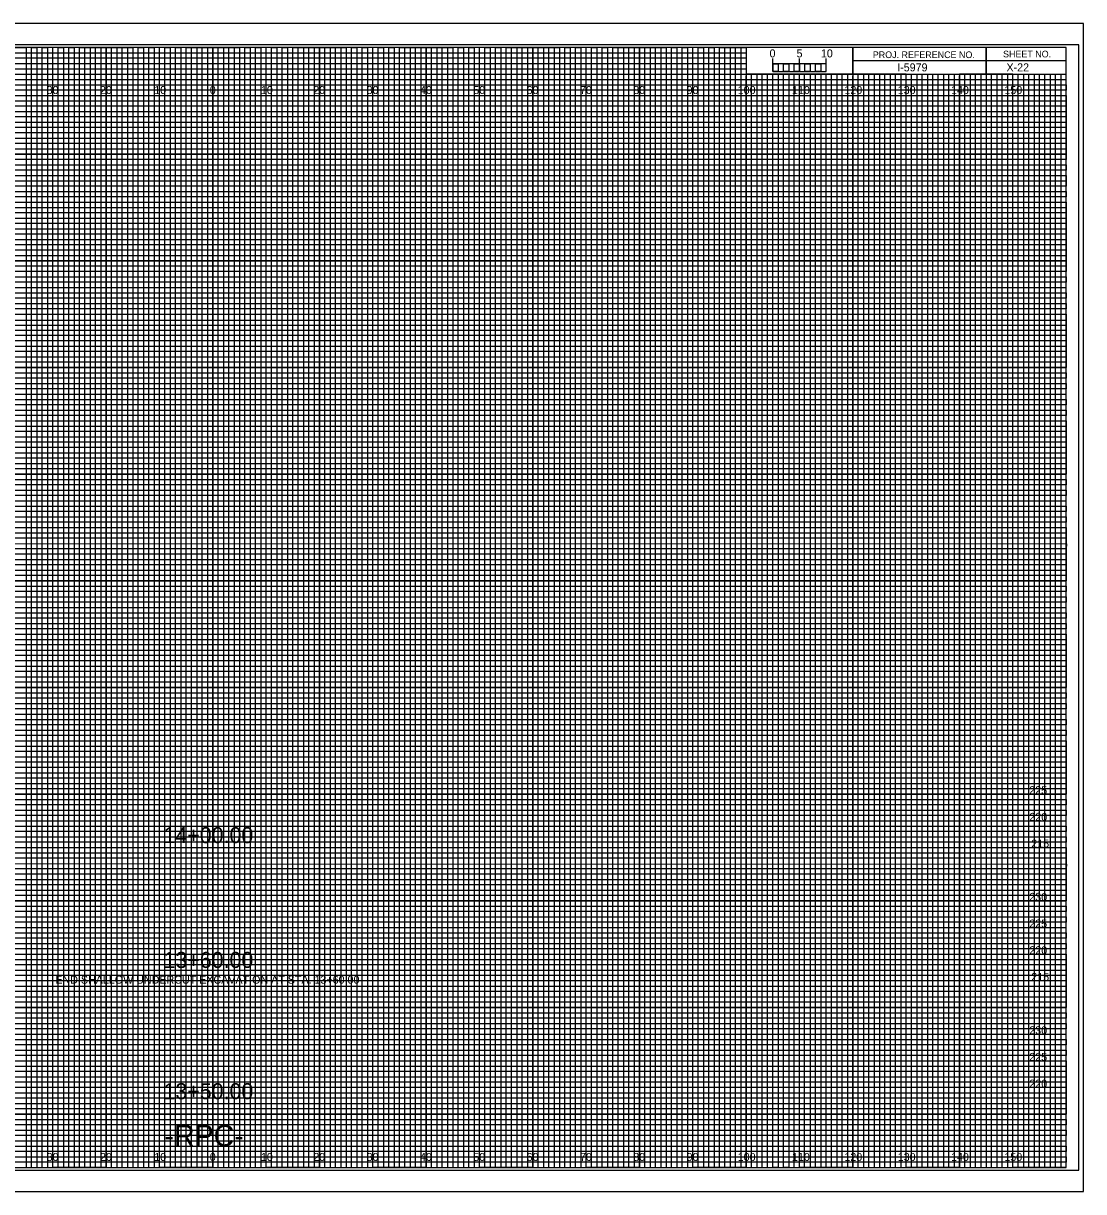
# Model space of a CAD drawing. Extents: x -13 to 323, y -5 to 434.
# Drawn here: x 124.5 to 323.3, y 215.5 to 434.5 of the extents above; entities that cross this region are included whole.
import ezdxf

# ---------------------------------------------------------------- set-up
doc = ezdxf.new("R2010")
doc.units = 0
for name, color, linetype in [('Prop XS Alignment Label', 7, 'Continuous'), ('Prop XS Bar Scale Labels', 7, 'Continuous'), ('Prop XS Elevation Labels', 7, 'Continuous'), ('Prop XS Hydro Elevations', 7, 'Continuous'), ('Prop XS Offset Labels', 7, 'Continuous'), ('Prop XS Project Number', 7, 'Continuous'), ('Prop XS Sheet Number', 7, 'Continuous'), ('Prop XS Station Labels', 7, 'Continuous'), ('Sheet Cross Section CELL', 7, 'Continuous'), ('Sheet Cross Section Grid Major CELL', 7, 'Continuous'), ('Sheet Cross Section Grid Middle CELL', 7, 'Continuous'), ('Sheet Cross Section Grid Minor 1 CELL', 7, 'Continuous'), ('Sheet Cross Section Grid Minor 2 CELL', 7, 'Continuous'), ('Sheet Cross Section Scale CELL', 7, 'Continuous'), ('Sheet Cutting Line CELL', 7, 'Continuous'), ('Sheet DOT Grid CELL', 7, 'Continuous'), ('Sheet Plot Border Inside CELL', 7, 'Continuous'), ('Sheet Plot Border Outside CELL', 7, 'Continuous')]:
    doc.layers.add(name, color=color, linetype=linetype)

msp = doc.modelspace()

# ---------------------------------------------------------------- linework, layer by layer
at = {"layer": 'Sheet Cross Section CELL'}
for p, q in [((305, 430), (305, 425)), ((305, 425), (305, 430)), ((280, 427.5), (280, 425)), ((320, 427.49), (280, 427.49)), ((280, 425), (320, 425))]:
    msp.add_line(p, q, dxfattribs=at)
for points in [[(320, 430), (0, 430), (0, 220), (320, 220)], [(280, 430), (260, 430), (260, 425.03), (280, 425.03)], [(320, 430), (280, 430), (280, 425), (320, 425)]]:
    msp.add_lwpolyline(points, close=True, dxfattribs=at)
at = {"layer": 'Sheet Cross Section Grid Major CELL'}
for p, q in [((130, 430), (120, 430)), ((130, 220), (130, 430)), ((150, 430), (140, 430)), ((140, 430), (140, 220)), ((150, 220), (150, 430)), ((170, 430), (160, 430)), ((160, 430), (160, 220)), ((170, 220), (170, 430)), ((190, 430), (180, 430)), ((180, 430), (180, 220)), ((190, 220), (190, 430)), ((210, 430), (200, 430)), ((200, 430), (200, 220)), ((210, 220), (210, 430)), ((230, 430), (220, 430)), ((220, 430), (220, 220)), ((230, 220), (230, 430)), ((250, 430), (240, 430)), ((240, 430), (240, 220)), ((250, 220), (250, 430)), ((260, 430), (260, 220)), ((270, 220), (270, 425)), ((290, 425), (280, 425)), ((280, 425), (280, 220)), ((290, 220), (290, 425)), ((310, 425), (300, 425)), ((300, 425), (300, 220)), ((310, 220), (310, 425)), ((140, 220), (130, 220)), ((160, 220), (150, 220)), ((180, 220), (170, 220)), ((200, 220), (190, 220)), ((220, 220), (210, 220)), ((240, 220), (230, 220)), ((260, 220), (250, 220)), ((280, 220), (270, 220)), ((300, 220), (290, 220)), ((320, 220), (310, 220)), ((320, 220), (320, 220))]:
    msp.add_line(p, q, dxfattribs=at)
for points in [[(0, 420), (320, 420), (320, 410), (0, 410)], [(0, 400), (320, 400), (320, 390), (0, 390)], [(0, 380), (320, 380), (320, 370), (0, 370)], [(0, 360), (320, 360), (320, 350), (0, 350)], [(0, 340), (320, 340), (320, 330), (0, 330)], [(0, 320), (320, 320), (320, 310), (0, 310)], [(0, 300), (320, 300), (320, 290), (0, 290)], [(0, 280), (320, 280), (320, 270), (0, 270)], [(0, 260), (320, 260), (320, 250), (0, 250)], [(0, 240), (320, 240), (320, 230), (0, 230)]]:
    msp.add_lwpolyline(points, dxfattribs=at)
at = {"layer": 'Sheet Cross Section Grid Middle CELL'}
for points in [[(115, 430), (125, 430), (125, 220), (135, 220), (135, 430), (145, 430), (145, 220), (155, 220), (155, 430), (165, 430), (165, 220), (175, 220), (175, 430), (185, 430), (185, 220), (195, 220), (195, 430), (205, 430), (205, 220), (215, 220), (215, 430), (225, 430), (225, 220), (235, 220), (235, 430), (245, 430), (245, 220), (255, 220), (255, 430), (259.93, 430), (260, 430), (260, 425), (264.99, 425), (264.99, 220), (275, 220), (275, 425), (285, 425), (285, 220), (295, 220), (295, 425), (305, 425), (305, 220), (315, 220), (315, 425)], [(0, 425), (275, 425)], [(0, 405), (320, 405), (320, 415), (0, 415)], [(0, 385), (320, 385), (320, 395), (0, 395)], [(0, 365), (320, 365), (320, 375), (0, 375)], [(0, 345), (320, 345), (320, 355), (0, 355)], [(0, 325), (320, 325), (320, 335), (0, 335)], [(0, 305), (320, 305), (320, 315), (0, 315)], [(0, 285), (320, 285), (320, 295), (0, 295)], [(0, 265), (320, 265), (320, 275), (0, 275)], [(0, 245), (320, 245), (320, 255), (0, 255)], [(0, 225), (320, 225), (320, 235), (0, 235)]]:
    msp.add_lwpolyline(points, dxfattribs=at)
at = {"layer": 'Sheet Cross Section Grid Minor 1 CELL'}
for p, q in [((0, 429), (260, 429)), ((260, 427.98), (0, 427.98)), ((260, 429), (260, 427.98)), ((0, 427), (260, 427)), ((260, 425.89), (0, 425.89)), ((260, 427), (260, 425.89)), ((0, 424), (320, 424))]:
    msp.add_line(p, q, dxfattribs=at)
for points in [[(0, 423), (270, 423), (320, 423), (320, 422), (0, 422)], [(0, 421), (320, 421), (320, 419), (0, 419)], [(0, 418), (320, 418), (320, 417), (0, 416.98)], [(0, 416), (320, 416), (320, 414), (0, 414)], [(0, 413), (320, 413), (320, 412), (0, 412)], [(0, 411), (320, 411), (320, 409), (0, 409)], [(0, 408), (320, 408), (320, 407), (0, 407)], [(0, 406), (320, 406), (320, 404), (0, 404)], [(0, 403), (320, 403), (320, 402), (0, 402)], [(0, 401), (320, 401), (320, 399), (0, 399)], [(0, 398), (320, 398), (320, 397), (0, 397)], [(0, 396), (320, 396), (320, 393.95), (320, 393), (320, 392), (0, 392)], [(0, 394), (320, 394), (320, 393), (0, 393)], [(0, 391), (320, 391), (320, 389), (0, 389.03)], [(0, 389.03), (320, 389), (320, 388), (0, 388)], [(0, 387), (320, 387), (320, 386), (0, 386)], [(0, 384), (320, 384), (320, 383), (0, 383)], [(0, 382), (320, 382), (320, 381), (0, 381)], [(-0.07, 378.89), (320, 378.89), (320, 377.88), (-0.07, 377.88)], [(0, 377), (320, 377), (320, 376), (0, 376)], [(0, 374), (320, 374), (320, 373), (0, 373)], [(0, 372), (320, 372), (320, 371), (0, 371)], [(0, 369), (320, 369), (320, 368), (0, 368)], [(0, 367), (320, 367), (320, 366), (0, 366)], [(0, 364), (320, 364), (320, 363), (0, 363)], [(0, 362), (320, 362), (320, 361), (0, 361)], [(0, 359), (320, 359), (319.99, 357.98), (0, 358)], [(0, 357), (320, 357), (320, 356), (0, 356)], [(0, 354), (320, 354), (320, 353), (0, 353)], [(0, 352), (320, 352), (320, 351), (0, 351)], [(0, 349), (320, 349), (320, 348), (0, 348)], [(0, 347), (320, 347), (320, 346), (0, 346)], [(0, 344), (320, 344), (320, 343), (0, 343)], [(0, 342), (320, 342), (320, 341), (0, 341)], [(0, 339), (320, 339), (320, 338), (0, 338)], [(0, 336.99), (320.07, 336.91), (320, 336), (0, 336)], [(0, 334), (320, 334), (320, 333), (0, 333)], [(0, 332), (320, 332), (320, 331), (0, 331)], [(0, 329), (320, 329), (320, 328), (0, 328)], [(0, 327), (320, 327), (320, 326), (0, 326)], [(0, 324), (320, 324), (320, 323), (0, 323)], [(0, 322), (320, 322), (320, 321), (0, 321)], [(0, 319), (320, 319), (320, 318), (0, 318)], [(0, 317), (320, 317), (320, 316), (0, 316)], [(0, 314), (320, 314), (320, 313), (0, 313)], [(0, 312), (320, 312), (320, 311), (0, 311)], [(0, 309), (320, 309), (320, 308), (0, 308)], [(0, 307), (320, 307), (320, 306), (0, 306)], [(0, 304), (320, 304), (320, 303), (0, 303)], [(0, 302), (320, 302), (320, 301), (0, 301)], [(0, 299), (320, 299), (319.99, 297.98), (0, 298)], [(0, 297), (320, 297), (320, 296), (0, 296)], [(0, 294), (320, 294), (320, 293), (0, 293)], [(0, 292), (320, 292), (320, 291), (0, 291)], [(0, 289), (320, 289), (320, 288), (0, 288)], [(0, 287), (320, 287), (320, 286), (0, 286)], [(0, 284), (320, 284), (320, 283), (0, 283)], [(0, 282), (320, 282), (320, 281), (0, 281)], [(0, 279), (320, 279), (320, 278), (0, 278)], [(0, 276.99), (320.07, 276.91), (320, 276), (0, 276)], [(0, 274), (320, 274), (320, 273), (0, 273)], [(0, 272), (320, 272), (320, 271), (0, 271)], [(0, 269), (320, 269), (320, 268), (0, 268)], [(0, 267), (320, 267), (320, 266), (0, 266)], [(0, 264), (320, 264), (320, 263), (0, 263)], [(0, 262), (320, 262), (320, 261), (0, 261)], [(0, 259), (320, 259), (320, 258), (0, 258)], [(0, 257), (320, 257), (320, 256), (0, 256)], [(0, 254), (320, 254), (320, 253), (0, 253)], [(0, 252), (320, 252), (320, 251), (0, 251)], [(0, 249), (320, 249), (320, 248), (0, 248)], [(0, 247), (320, 247), (320, 246), (0, 246)], [(0, 244), (320, 244), (320, 243), (0, 243)], [(0, 242), (320, 242), (320, 241), (0, 241)], [(0, 239), (320, 239), (320, 238), (0, 238)], [(0, 237), (320, 237), (320, 236), (0, 236)], [(0, 234), (320, 234), (320, 233), (0, 233)], [(0, 232), (320, 232), (320, 231), (0, 231)], [(0, 229), (320, 229), (320, 228), (0, 228)], [(0, 227), (320, 227), (320, 226), (0, 226)], [(0, 224), (320, 224), (320, 223), (0, 223)], [(0, 222), (320, 222), (320, 221), (0, 221)]]:
    msp.add_lwpolyline(points, dxfattribs=at)
at = {"layer": 'Sheet Cross Section Grid Minor 2 CELL'}
for p, q in [((267, 425), (266.01, 425)), ((266.01, 425), (266.01, 220)), ((267, 220), (267, 425)), ((269, 425), (268, 425)), ((268, 425), (268, 220)), ((269, 220), (269, 425)), ((266.01, 220), (265, 220)), ((268, 220), (267, 220))]:
    msp.add_line(p, q, dxfattribs=at)
for points in [[(125, 220), (126, 220), (126, 430), (127, 430), (127, 220)], [(127, 220), (128, 220), (128, 430), (129, 430), (129, 220)], [(130, 220), (131, 220), (131, 430), (132, 430), (132, 220)], [(132, 220), (133, 220), (133, 430), (134, 430), (134, 220)], [(135, 220), (136, 220), (136, 430), (137, 430), (137, 220)], [(137, 220), (138, 220), (138, 430), (139, 430), (139, 220)], [(140, 220), (141, 220), (141, 430), (142, 430), (142, 220)], [(142, 220), (143, 220), (143, 430), (144, 430), (144, 220)], [(145, 220), (146, 220), (146, 430), (147, 430), (147, 220)], [(147, 220), (148, 220), (148, 430), (149, 430), (149, 220)], [(150, 220), (151, 220), (151, 430), (152, 430), (152, 220)], [(152, 220), (153, 220), (153, 430), (154, 430), (154, 220)], [(155, 220), (156, 220), (156, 430), (157, 430), (157, 220)], [(157, 220), (158, 220), (158, 430), (159, 430), (159, 220)], [(160, 220), (161, 220), (161, 430), (162, 430), (162, 220)], [(162, 220), (163, 220), (163, 430), (164, 430), (164, 220)], [(165, 220), (166, 220), (166, 430), (167, 430), (167, 220)], [(167, 220), (168, 220), (168, 430), (169, 430), (169, 220)], [(170, 220), (171, 220), (171, 430), (172, 430), (172, 220)], [(172, 220), (173, 220), (173, 430), (174, 430), (174, 220)], [(175, 220), (176, 220), (176, 430), (177, 430), (177, 220)], [(177, 220), (178, 220), (178, 430), (179, 430), (179, 220)], [(180, 220), (181, 220), (181, 430), (182, 430), (182, 220)], [(182, 220), (183, 220), (183, 430), (184, 430), (184, 220)], [(185, 220), (186, 220), (186, 430), (187, 430), (187, 220)], [(187, 220), (188, 220), (188, 430), (189, 430), (189, 220)], [(190, 220), (191, 220), (191, 430), (192, 430), (192, 220)], [(192, 220), (193, 220), (193, 430), (194, 430), (194, 220)], [(195, 220), (196, 220), (196, 430), (197, 430), (197, 220)], [(197, 220), (198, 220), (198, 430), (199, 430), (199, 220)], [(200, 220), (201, 220), (201, 430), (202, 430), (202, 220)], [(202, 220), (203, 220), (203, 430), (204, 430), (204, 220)], [(205, 220), (206, 220), (206, 430), (207, 430), (207, 220)], [(207, 220), (208, 220), (208, 430), (209, 430), (209, 220)], [(210, 220), (211, 220), (211, 430), (212, 430), (212, 220)], [(212, 220), (213, 220), (213, 430), (214, 430), (214, 220)], [(215, 220), (216, 220), (216, 430), (217, 430), (217, 220)], [(217, 220), (218, 220), (218, 430), (219, 430), (219, 220)], [(220, 220), (221, 220), (221, 430), (222, 430), (222, 220)], [(222, 220), (223, 220), (223, 430), (224, 430), (224, 220)], [(225, 220), (226, 220), (226, 430), (227, 430), (227, 220)], [(227, 220), (228, 220), (228, 430), (229, 430), (229, 220)], [(230, 220), (231, 220), (231, 430), (232, 430), (232, 220)], [(232, 220), (233, 220), (233, 430), (234, 430), (234, 220)], [(235, 220), (236, 220), (236, 430), (237, 430), (237, 220)], [(237, 220), (238, 220), (238, 430), (239, 430), (239, 220)], [(240, 220), (241, 220), (241, 430), (242, 430), (242, 220)], [(242, 220), (243, 220), (243, 430), (244, 430), (244, 220)], [(245, 220), (246, 220), (246, 430), (247, 430), (247, 220)], [(247, 220), (248, 220), (248, 430), (249, 430), (249, 220)], [(250, 220), (251, 220), (251, 430), (252, 430), (252, 220)], [(252, 220), (253, 220), (253, 430), (254, 430), (254, 220)], [(255, 220), (256, 220), (256, 430), (257, 430), (257, 220)], [(257, 220), (258, 220), (258, 430), (259, 430), (259, 220)], [(260, 220), (261, 220), (261, 425), (262.02, 425), (262.02, 220)], [(262, 220), (263, 220), (263, 425), (263.99, 425), (263.99, 220)], [(270, 220), (270.98, 220), (270.98, 425), (272, 425), (272, 220)], [(272, 220), (273, 220), (273, 425), (274.05, 425), (274.05, 220)], [(275, 220), (276, 220), (276, 425), (277, 425), (277, 220)], [(277, 220), (278, 220), (278, 425), (279, 425), (279, 220)], [(280, 220), (281, 220), (281, 425), (282, 425), (282, 220)], [(282, 220), (283, 220), (283, 425), (284, 425), (284, 220)], [(285, 220), (286, 220), (286, 425), (287, 425), (287, 220)], [(287, 220), (288, 220), (288, 425), (289, 425), (289, 220)], [(290, 220), (291, 220), (291, 425), (292, 425), (292, 220)], [(292, 220), (293, 220), (293, 425), (294, 425), (294, 220)], [(295, 220), (296, 220), (296, 425), (297, 425), (297, 220)], [(297, 220), (298, 220), (298, 425), (299, 425), (299, 220)], [(300, 220), (301, 220), (301, 425), (302, 425), (302, 220)], [(302, 220), (303, 220), (303, 425), (304, 425), (304, 220)], [(305, 220), (306, 220), (306, 425), (307, 425), (307, 220)], [(307, 220), (308, 220), (308, 425), (309, 425), (309, 220)], [(310, 220), (311, 220), (311, 425), (312, 425), (312, 220)], [(312, 220), (313, 220), (313, 425), (314, 425), (314, 220)], [(315, 220), (316, 220), (316, 425), (317, 425), (317, 220)], [(317, 220), (318, 220), (318, 425), (319, 425), (319, 220)]]:
    msp.add_lwpolyline(points, dxfattribs=at)
at = {"layer": 'Sheet Cross Section Scale CELL'}
for p, q in [((265, 425.49), (265, 427.9)), ((265, 426.9), (265, 427.9)), ((270, 425.49), (270, 427.9)), ((275, 425.49), (275, 427.9)), ((275, 426.9), (275, 427.9))]:
    msp.add_line(p, q, dxfattribs=at)
for points in [[(275, 426.9), (265, 426.9), (265, 425.49), (275, 425.49)], [(265, 426.9), (266, 426.9), (266, 425.49), (265, 425.49)], [(267, 426.9), (268, 426.9), (268, 425.49), (267, 425.49)], [(269, 426.9), (270, 426.9), (270, 425.49), (269, 425.49)], [(271, 426.9), (272, 426.9), (272, 425.49), (271, 425.49)], [(273, 426.9), (274, 426.9), (274, 425.49), (273, 425.49)]]:
    msp.add_lwpolyline(points, close=True, dxfattribs=at)
at = {"layer": 'Sheet Cutting Line CELL'}
for p, q in [((323.3, 434.5), (-13.4, 434.5)), ((-13.4, 215.5), (323.3, 215.5))]:
    msp.add_line(p, q, dxfattribs=at)
at = {"layer": 'Sheet DOT Grid CELL'}
for p, q in [((130, 220), (130, 430)), ((140, 220), (140, 430)), ((150, 220), (150, 430)), ((160, 220), (160, 430)), ((170, 220), (170, 430)), ((180, 220), (180, 430)), ((190, 220), (190, 430)), ((200, 220), (200, 430)), ((210, 220), (210, 430)), ((220, 220), (220, 430)), ((230, 220), (230, 430)), ((240, 220), (240, 430)), ((250, 220), (250, 430)), ((260, 220), (260, 424.69)), ((270, 220), (270, 424.69)), ((280, 220), (280, 424.69)), ((290, 220), (290, 424.69)), ((300, 220), (300, 424.69)), ((310, 220), (310, 424.69)), ((0, 420), (320, 420)), ((0, 410), (320, 410)), ((0, 400), (320, 400)), ((0, 390), (320, 390)), ((0, 380), (320, 380)), ((0, 370), (320, 370)), ((0, 360), (320, 360)), ((0, 350), (320, 350)), ((0, 340), (320, 340)), ((0, 330), (320, 330)), ((0, 320), (320, 320)), ((0, 310), (320, 310)), ((0, 300), (320, 300)), ((0, 290), (320, 290)), ((0, 280), (320, 280)), ((0, 270), (320, 270)), ((0, 260), (320, 260)), ((0, 250), (320, 250)), ((0, 240), (320, 240)), ((0, 230), (320, 230))]:
    msp.add_line(p, q, dxfattribs=at)
at = {"layer": 'Sheet Plot Border Inside CELL'}
msp.add_lwpolyline([(-10.8, 219.5), (322.4, 219.5), (322.4, 430.5), (-10.8, 430.5)], close=True, dxfattribs=at)
at = {"layer": 'Sheet Plot Border Outside CELL'}
msp.add_lwpolyline([(-13.4, 215.5), (323.3, 215.5), (323.3, 434.5), (-13.4, 434.5)], close=True, dxfattribs=at)

# ---------------------------------------------------------------- texts
at = {"layer": 'Prop XS Alignment Label'}
msp.add_text('-RPC-', height=4, dxfattribs=at).set_placement((150.97, 224))
at = {"layer": 'Prop XS Bar Scale Labels'}
for s, p in [('5', (269.47, 428.12)), ('10', (274.04, 428.12))]:
    msp.add_text(s, height=1.5, dxfattribs=at).set_placement(p)
at = {"layer": 'Prop XS Elevation Labels'}
for s, p in [('225', (313.1, 290)), ('220', (313.12, 285)), ('215', (313.48, 280)), ('230', (313.11, 270)), ('225', (313.1, 265)), ('220', (313.12, 260)), ('215', (313.48, 255)), ('230', (313.11, 245)), ('225', (313.1, 240)), ('220', (313.12, 235))]:
    msp.add_text(s, height=1.5, dxfattribs=at).set_placement(p)
at = {"layer": 'Prop XS Hydro Elevations'}
msp.add_text('END SHALLOW UNDERCUT EXCAVATION AT STA. 13+60.00', height=1.5, dxfattribs=at).set_placement((130.5, 254.48))
at = {"layer": 'Prop XS Offset Labels'}
for s, p in [('30', (128.86, 421.25)), ('20', (138.86, 421.25)), ('10', (149.04, 421.25)), ('0', (159.45, 421.25)), ('0', (159.45, 421.25)), ('10', (169.04, 421.25)), ('20', (178.86, 421.25)), ('30', (188.86, 421.25)), ('40', (198.86, 421.25)), ('50', (208.86, 421.25)), ('60', (218.86, 421.25)), ('70', (228.86, 421.25)), ('80', (238.86, 421.25)), ('90', (248.86, 421.25)), ('100', (258.44, 421.25)), ('110', (268.62, 421.25)), ('120', (278.44, 421.25)), ('130', (288.44, 421.25)), ('140', (298.44, 421.25)), ('150', (308.44, 421.25)), ('30', (128.86, 221.25)), ('20', (138.86, 221.25)), ('10', (149.04, 221.25)), ('0', (159.45, 221.25)), ('0', (159.45, 221.25)), ('10', (169.04, 221.25)), ('20', (178.86, 221.25)), ('30', (188.86, 221.25)), ('40', (198.86, 221.25)), ('50', (208.86, 221.25)), ('60', (218.86, 221.25)), ('70', (228.86, 221.25)), ('80', (238.86, 221.25)), ('90', (248.86, 221.25)), ('100', (258.44, 221.25)), ('110', (268.62, 221.25)), ('120', (278.44, 221.25)), ('130', (288.44, 221.25)), ('140', (298.44, 221.25)), ('150', (308.44, 221.25))]:
    msp.add_text(s, height=1.5, dxfattribs=at).set_placement(p)
at = {"layer": 'Prop XS Project Number'}
msp.add_text('I-5979', height=1.5, dxfattribs=at).set_placement((288.34, 425.5))
at = {"layer": 'Prop XS Sheet Number'}
msp.add_text('X-22', height=1.5, dxfattribs=at).set_placement((308.83, 425.5))
at = {"layer": 'Prop XS Station Labels'}
for s, p in [('14+00.00', (150.77, 280.83)), ('13+60.00', (150.77, 257.43)), ('13+50.00', (150.77, 232.83))]:
    msp.add_text(s, height=3, dxfattribs=at).set_placement(p)
at = {"layer": 'Sheet Cross Section CELL'}
for s, p in [('PROJ. REFERENCE NO.', (283.77, 427.99)), ('SHEET NO.', (308.19, 428.12))]:
    msp.add_text(s, height=1.25, dxfattribs=at).set_placement(p)
at = {"layer": 'Sheet Cross Section Scale CELL'}
msp.add_text('0', height=1.5, dxfattribs=at).set_placement((264.41, 428.12))

doc.saveas('drawing.dxf')
